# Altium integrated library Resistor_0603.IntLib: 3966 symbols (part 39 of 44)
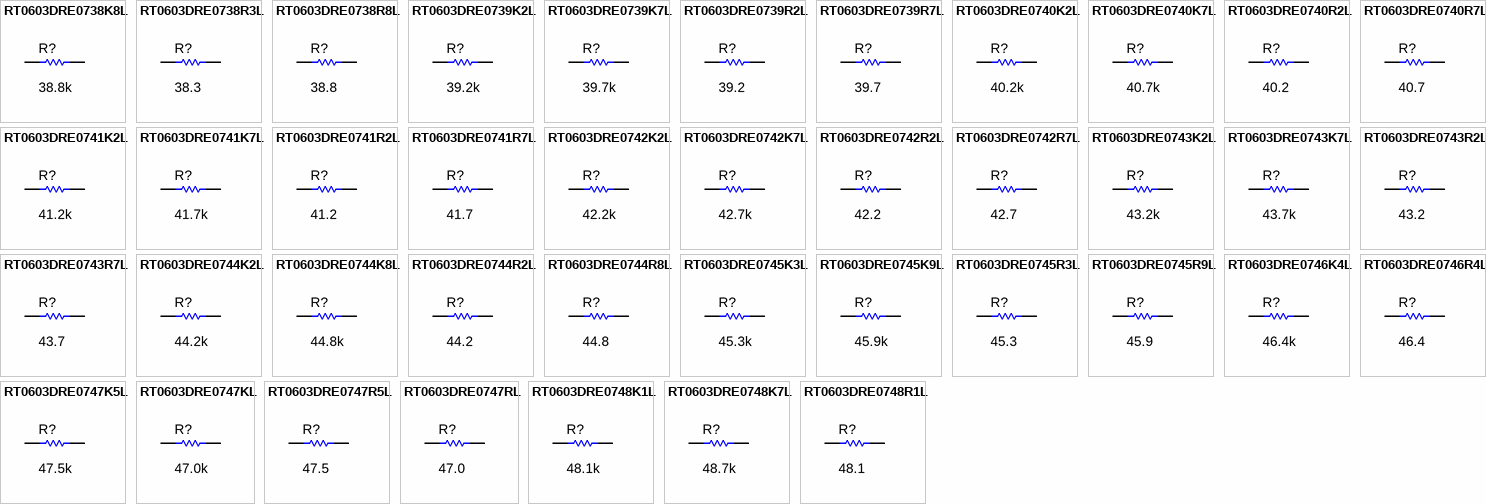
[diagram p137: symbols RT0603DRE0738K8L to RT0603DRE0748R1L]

## RT0603DRE0745R9L
designator R?  ValueDisplayed: 45.9  (hidden comment: RT0603DRE0745R9L)
RES, 45.9, 0.5%, 0.1 W, 0603; Manufacturer: Yageo America; CompType: Resistor; Value: 45.9; Value_Code: 45R9; Tolerance_%: 0.5; Power_W: 0.1; Value2: 0.1W; VDC_V: 75; TempCo: 50 ppm/C; SizeArea_mm2: 1.28; SizeX_mm: 1.6; SizeY_mm: 0.8; SizeZ_mm: 1; EIA_Code: E192; U/M: EA; AEC Category: Q200
signal-integrity model Resistor
simulation model Resistor
footprint 0603
footprint 0603M
footprint 0603L
footprint 0603_HV
footprint 0603S
pins: 1, 2

## RT0603DRE0746K4L
designator R?  ValueDisplayed: 46.4k  (hidden comment: RT0603DRE0746K4L)
RES, 46.4 k, 0.5%, 0.1 W, 0603; Manufacturer: Yageo America; CompType: Resistor; Value: 46.4k; Res_ohm: 46400; Value_Code: 46k4; Tolerance_%: 0.5; Power_W: 0.1; Value2: 0.1W; VDC_V: 75; TempCo: 50 ppm/C; SizeArea_mm2: 1.28; SizeX_mm: 1.6; SizeY_mm: 0.8; SizeZ_mm: 1; EIA_Code: E192; U/M: EA; AEC Category: Q200
signal-integrity model Resistor
simulation model Resistor
footprint 0603
footprint 0603M
footprint 0603L
footprint 0603_HV
footprint 0603S
pins: 1, 2

## RT0603DRE0746R4L
designator R?  ValueDisplayed: 46.4  (hidden comment: RT0603DRE0746R4L)
RES, 46.4, 0.5%, 0.1 W, 0603; Manufacturer: Yageo America; CompType: Resistor; Value: 46.4; Value_Code: 46R4; Tolerance_%: 0.5; Power_W: 0.1; Value2: 0.1W; VDC_V: 75; TempCo: 50 ppm/C; SizeArea_mm2: 1.28; SizeX_mm: 1.6; SizeY_mm: 0.8; SizeZ_mm: 1; EIA_Code: E192; U/M: EA; AEC Category: Q200
signal-integrity model Resistor
simulation model Resistor
footprint 0603
footprint 0603M
footprint 0603L
footprint 0603_HV
footprint 0603S
pins: 1, 2

## RT0603DRE0747K5L
designator R?  ValueDisplayed: 47.5k  (hidden comment: RT0603DRE0747K5L)
RES, 47.5 k, 0.5%, 0.1 W, 0603; Manufacturer: Yageo America; CompType: Resistor; Value: 47.5k; Res_ohm: 47500; Value_Code: 47k5; Tolerance_%: 0.5; Power_W: 0.1; Value2: 0.1W; VDC_V: 75; TempCo: 50 ppm/C; SizeArea_mm2: 1.28; SizeX_mm: 1.6; SizeY_mm: 0.8; SizeZ_mm: 1; EIA_Code: E192; U/M: EA; AEC Category: Q200
signal-integrity model Resistor
simulation model Resistor
footprint 0603
footprint 0603M
footprint 0603L
footprint 0603_HV
footprint 0603S
pins: 1, 2

## RT0603DRE0747KL
designator R?  ValueDisplayed: 47.0k  (hidden comment: RT0603DRE0747KL)
RES, 47.0 k, 0.5%, 0.1 W, 0603; Manufacturer: Yageo America; CompType: Resistor; Value: 47.0k; Res_ohm: 47000; Value_Code: 47k0; Tolerance_%: 0.5; Power_W: 0.1; Value2: 0.1W; VDC_V: 75; TempCo: 50 ppm/C; SizeArea_mm2: 1.28; SizeX_mm: 1.6; SizeY_mm: 0.8; SizeZ_mm: 1; EIA_Code: E192; U/M: EA; AEC Category: Q200
signal-integrity model Resistor
simulation model Resistor
footprint 0603
footprint 0603M
footprint 0603L
footprint 0603_HV
footprint 0603S
pins: 1, 2

## RT0603DRE0747R5L
designator R?  ValueDisplayed: 47.5  (hidden comment: RT0603DRE0747R5L)
RES, 47.5, 0.5%, 0.1 W, 0603; Manufacturer: Yageo America; CompType: Resistor; Value: 47.5; Value_Code: 47R5; Tolerance_%: 0.5; Power_W: 0.1; Value2: 0.1W; VDC_V: 75; TempCo: 50 ppm/C; SizeArea_mm2: 1.28; SizeX_mm: 1.6; SizeY_mm: 0.8; SizeZ_mm: 1; EIA_Code: E192; U/M: EA; AEC Category: Q200
signal-integrity model Resistor
simulation model Resistor
footprint 0603
footprint 0603M
footprint 0603L
footprint 0603_HV
footprint 0603S
pins: 1, 2

## RT0603DRE0747RL
designator R?  ValueDisplayed: 47.0  (hidden comment: RT0603DRE0747RL)
RES, 47.0, 0.5%, 0.1 W, 0603; Manufacturer: Yageo America; CompType: Resistor; Value: 47.0; Res_ohm: 47; Value_Code: 47R0; Tolerance_%: 0.5; Power_W: 0.1; Value2: 0.1W; VDC_V: 75; TempCo: 50 ppm/C; SizeArea_mm2: 1.28; SizeX_mm: 1.6; SizeY_mm: 0.8; SizeZ_mm: 1; EIA_Code: E192; U/M: EA; AEC Category: Q200
signal-integrity model Resistor
simulation model Resistor
footprint 0603
footprint 0603M
footprint 0603L
footprint 0603_HV
footprint 0603S
pins: 1, 2

## RT0603DRE0748K1L
designator R?  ValueDisplayed: 48.1k  (hidden comment: RT0603DRE0748K1L)
RES, 48.1 k, 0.5%, 0.1 W, 0603; Manufacturer: Yageo America; CompType: Resistor; Value: 48.1k; Res_ohm: 48100; Value_Code: 48k1; Tolerance_%: 0.5; Power_W: 0.1; Value2: 0.1W; VDC_V: 75; TempCo: 50 ppm/C; SizeArea_mm2: 1.28; SizeX_mm: 1.6; SizeY_mm: 0.8; SizeZ_mm: 1; EIA_Code: E192; U/M: EA; AEC Category: Q200
signal-integrity model Resistor
simulation model Resistor
footprint 0603
footprint 0603M
footprint 0603L
footprint 0603_HV
footprint 0603S
pins: 1, 2

## RT0603DRE0748K7L
designator R?  ValueDisplayed: 48.7k  (hidden comment: RT0603DRE0748K7L)
RES, 48.7 k, 0.5%, 0.1 W, 0603; Manufacturer: Yageo America; CompType: Resistor; Value: 48.7k; Res_ohm: 48700; Value_Code: 48k7; Tolerance_%: 0.5; Power_W: 0.1; Value2: 0.1W; VDC_V: 75; TempCo: 50 ppm/C; SizeArea_mm2: 1.28; SizeX_mm: 1.6; SizeY_mm: 0.8; SizeZ_mm: 1; EIA_Code: E192; U/M: EA; AEC Category: Q200
signal-integrity model Resistor
simulation model Resistor
footprint 0603
footprint 0603M
footprint 0603L
footprint 0603_HV
footprint 0603S
pins: 1, 2

## RT0603DRE0748R1L
designator R?  ValueDisplayed: 48.1  (hidden comment: RT0603DRE0748R1L)
RES, 48.1, 0.5%, 0.1 W, 0603; Manufacturer: Yageo America; CompType: Resistor; Value: 48.1; Value_Code: 48R1; Tolerance_%: 0.5; Power_W: 0.1; Value2: 0.1W; VDC_V: 75; TempCo: 50 ppm/C; SizeArea_mm2: 1.28; SizeX_mm: 1.6; SizeY_mm: 0.8; SizeZ_mm: 1; EIA_Code: E192; U/M: EA; AEC Category: Q200
signal-integrity model Resistor
simulation model Resistor
footprint 0603
footprint 0603M
footprint 0603L
footprint 0603_HV
footprint 0603S
pins: 1, 2

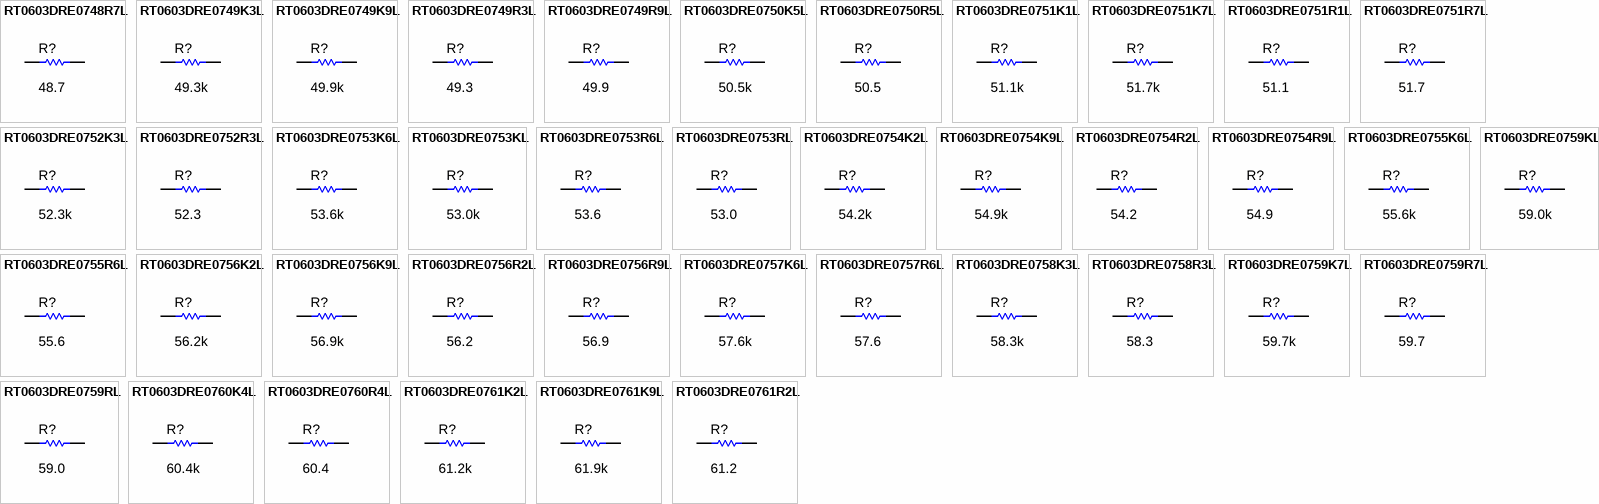
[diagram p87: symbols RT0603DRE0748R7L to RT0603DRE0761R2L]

## RT0603DRE0748R7L
designator R?  ValueDisplayed: 48.7  (hidden comment: RT0603DRE0748R7L)
RES, 48.7, 0.5%, 0.1 W, 0603; Manufacturer: Yageo America; CompType: Resistor; Value: 48.7; Value_Code: 48R7; Tolerance_%: 0.5; Power_W: 0.1; Value2: 0.1W; VDC_V: 75; TempCo: 50 ppm/C; SizeArea_mm2: 1.28; SizeX_mm: 1.6; SizeY_mm: 0.8; SizeZ_mm: 1; EIA_Code: E192; U/M: EA; AEC Category: Q200
signal-integrity model Resistor
simulation model Resistor
footprint 0603
footprint 0603M
footprint 0603L
footprint 0603_HV
footprint 0603S
pins: 1, 2

## RT0603DRE0749K3L
designator R?  ValueDisplayed: 49.3k  (hidden comment: RT0603DRE0749K3L)
RES, 49.3 k, 0.5%, 0.1 W, 0603; Manufacturer: Yageo America; CompType: Resistor; Value: 49.3k; Res_ohm: 49300; Value_Code: 49k3; Tolerance_%: 0.5; Power_W: 0.1; Value2: 0.1W; VDC_V: 75; TempCo: 50 ppm/C; SizeArea_mm2: 1.28; SizeX_mm: 1.6; SizeY_mm: 0.8; SizeZ_mm: 1; EIA_Code: E192; U/M: EA; AEC Category: Q200
signal-integrity model Resistor
simulation model Resistor
footprint 0603
footprint 0603M
footprint 0603L
footprint 0603_HV
footprint 0603S
pins: 1, 2

## RT0603DRE0749K9L
designator R?  ValueDisplayed: 49.9k  (hidden comment: RT0603DRE0749K9L)
RES, 49.9 k, 0.5%, 0.1 W, 0603; Manufacturer: Yageo America; CompType: Resistor; Value: 49.9k; Res_ohm: 49900; Value_Code: 49k9; Tolerance_%: 0.5; Power_W: 0.1; Value2: 0.1W; VDC_V: 75; TempCo: 50 ppm/C; SizeArea_mm2: 1.28; SizeX_mm: 1.6; SizeY_mm: 0.8; SizeZ_mm: 1; EIA_Code: E192; U/M: EA; AEC Category: Q200
signal-integrity model Resistor
simulation model Resistor
footprint 0603
footprint 0603M
footprint 0603L
footprint 0603_HV
footprint 0603S
pins: 1, 2

## RT0603DRE0749R3L
designator R?  ValueDisplayed: 49.3  (hidden comment: RT0603DRE0749R3L)
RES, 49.3, 0.5%, 0.1 W, 0603; Manufacturer: Yageo America; CompType: Resistor; Value: 49.3; Value_Code: 49R3; Tolerance_%: 0.5; Power_W: 0.1; Value2: 0.1W; VDC_V: 75; TempCo: 50 ppm/C; SizeArea_mm2: 1.28; SizeX_mm: 1.6; SizeY_mm: 0.8; SizeZ_mm: 1; EIA_Code: E192; U/M: EA; AEC Category: Q200
signal-integrity model Resistor
simulation model Resistor
footprint 0603
footprint 0603M
footprint 0603L
footprint 0603_HV
footprint 0603S
pins: 1, 2

## RT0603DRE0749R9L
designator R?  ValueDisplayed: 49.9  (hidden comment: RT0603DRE0749R9L)
RES, 49.9, 0.5%, 0.1 W, 0603; Manufacturer: Yageo America; CompType: Resistor; Value: 49.9; Value_Code: 49R9; Tolerance_%: 0.5; Power_W: 0.1; Value2: 0.1W; VDC_V: 75; TempCo: 50 ppm/C; SizeArea_mm2: 1.28; SizeX_mm: 1.6; SizeY_mm: 0.8; SizeZ_mm: 1; EIA_Code: E192; U/M: EA; AEC Category: Q200
signal-integrity model Resistor
simulation model Resistor
footprint 0603
footprint 0603M
footprint 0603L
footprint 0603_HV
footprint 0603S
pins: 1, 2

## RT0603DRE0750K5L
designator R?  ValueDisplayed: 50.5k  (hidden comment: RT0603DRE0750K5L)
RES, 50.5 k, 0.5%, 0.1 W, 0603; Manufacturer: Yageo America; CompType: Resistor; Value: 50.5k; Res_ohm: 50500; Value_Code: 50k5; Tolerance_%: 0.5; Power_W: 0.1; Value2: 0.1W; VDC_V: 75; TempCo: 50 ppm/C; SizeArea_mm2: 1.28; SizeX_mm: 1.6; SizeY_mm: 0.8; SizeZ_mm: 1; EIA_Code: E192; U/M: EA; AEC Category: Q200
signal-integrity model Resistor
simulation model Resistor
footprint 0603
footprint 0603M
footprint 0603L
footprint 0603_HV
footprint 0603S
pins: 1, 2

## RT0603DRE0750R5L
designator R?  ValueDisplayed: 50.5  (hidden comment: RT0603DRE0750R5L)
RES, 50.5, 0.5%, 0.1 W, 0603; Manufacturer: Yageo America; CompType: Resistor; Value: 50.5; Value_Code: 50R5; Tolerance_%: 0.5; Power_W: 0.1; Value2: 0.1W; VDC_V: 75; TempCo: 50 ppm/C; SizeArea_mm2: 1.28; SizeX_mm: 1.6; SizeY_mm: 0.8; SizeZ_mm: 1; EIA_Code: E192; U/M: EA; AEC Category: Q200
signal-integrity model Resistor
simulation model Resistor
footprint 0603
footprint 0603M
footprint 0603L
footprint 0603_HV
footprint 0603S
pins: 1, 2

## RT0603DRE0751K1L
designator R?  ValueDisplayed: 51.1k  (hidden comment: RT0603DRE0751K1L)
RES, 51.1 k, 0.5%, 0.1 W, 0603; Manufacturer: Yageo America; CompType: Resistor; Value: 51.1k; Res_ohm: 51100; Value_Code: 51k1; Tolerance_%: 0.5; Power_W: 0.1; Value2: 0.1W; VDC_V: 75; TempCo: 50 ppm/C; SizeArea_mm2: 1.28; SizeX_mm: 1.6; SizeY_mm: 0.8; SizeZ_mm: 1; EIA_Code: E192; U/M: EA; AEC Category: Q200
signal-integrity model Resistor
simulation model Resistor
footprint 0603
footprint 0603M
footprint 0603L
footprint 0603_HV
footprint 0603S
pins: 1, 2

## RT0603DRE0751K7L
designator R?  ValueDisplayed: 51.7k  (hidden comment: RT0603DRE0751K7L)
RES, 51.7 k, 0.5%, 0.1 W, 0603; Manufacturer: Yageo America; CompType: Resistor; Value: 51.7k; Res_ohm: 51700; Value_Code: 51k7; Tolerance_%: 0.5; Power_W: 0.1; Value2: 0.1W; VDC_V: 75; TempCo: 50 ppm/C; SizeArea_mm2: 1.28; SizeX_mm: 1.6; SizeY_mm: 0.8; SizeZ_mm: 1; EIA_Code: E192; U/M: EA; AEC Category: Q200
signal-integrity model Resistor
simulation model Resistor
footprint 0603
footprint 0603M
footprint 0603L
footprint 0603_HV
footprint 0603S
pins: 1, 2

## RT0603DRE0751R1L
designator R?  ValueDisplayed: 51.1  (hidden comment: RT0603DRE0751R1L)
RES, 51.1, 0.5%, 0.1 W, 0603; Manufacturer: Yageo America; CompType: Resistor; Value: 51.1; Value_Code: 51R1; Tolerance_%: 0.5; Power_W: 0.1; Value2: 0.1W; VDC_V: 75; TempCo: 50 ppm/C; SizeArea_mm2: 1.28; SizeX_mm: 1.6; SizeY_mm: 0.8; SizeZ_mm: 1; EIA_Code: E192; U/M: EA; AEC Category: Q200
signal-integrity model Resistor
simulation model Resistor
footprint 0603
footprint 0603M
footprint 0603L
footprint 0603_HV
footprint 0603S
pins: 1, 2

## RT0603DRE0751R7L
designator R?  ValueDisplayed: 51.7  (hidden comment: RT0603DRE0751R7L)
RES, 51.7, 0.5%, 0.1 W, 0603; Manufacturer: Yageo America; CompType: Resistor; Value: 51.7; Value_Code: 51R7; Tolerance_%: 0.5; Power_W: 0.1; Value2: 0.1W; VDC_V: 75; TempCo: 50 ppm/C; SizeArea_mm2: 1.28; SizeX_mm: 1.6; SizeY_mm: 0.8; SizeZ_mm: 1; EIA_Code: E192; U/M: EA; AEC Category: Q200
signal-integrity model Resistor
simulation model Resistor
footprint 0603
footprint 0603M
footprint 0603L
footprint 0603_HV
footprint 0603S
pins: 1, 2

## RT0603DRE0752K3L
designator R?  ValueDisplayed: 52.3k  (hidden comment: RT0603DRE0752K3L)
RES, 52.3 k, 0.5%, 0.1 W, 0603; Manufacturer: Yageo America; CompType: Resistor; Value: 52.3k; Res_ohm: 52300; Value_Code: 52k3; Tolerance_%: 0.5; Power_W: 0.1; Value2: 0.1W; VDC_V: 75; TempCo: 50 ppm/C; SizeArea_mm2: 1.28; SizeX_mm: 1.6; SizeY_mm: 0.8; SizeZ_mm: 1; EIA_Code: E192; U/M: EA; AEC Category: Q200
signal-integrity model Resistor
simulation model Resistor
footprint 0603
footprint 0603M
footprint 0603L
footprint 0603_HV
footprint 0603S
pins: 1, 2

## RT0603DRE0752R3L
designator R?  ValueDisplayed: 52.3  (hidden comment: RT0603DRE0752R3L)
RES, 52.3, 0.5%, 0.1 W, 0603; Manufacturer: Yageo America; CompType: Resistor; Value: 52.3; Value_Code: 52R3; Tolerance_%: 0.5; Power_W: 0.1; Value2: 0.1W; VDC_V: 75; TempCo: 50 ppm/C; SizeArea_mm2: 1.28; SizeX_mm: 1.6; SizeY_mm: 0.8; SizeZ_mm: 1; EIA_Code: E192; U/M: EA; AEC Category: Q200
signal-integrity model Resistor
simulation model Resistor
footprint 0603
footprint 0603M
footprint 0603L
footprint 0603_HV
footprint 0603S
pins: 1, 2

## RT0603DRE0753K6L
designator R?  ValueDisplayed: 53.6k  (hidden comment: RT0603DRE0753K6L)
RES, 53.6 k, 0.5%, 0.1 W, 0603; Manufacturer: Yageo America; CompType: Resistor; Value: 53.6k; Res_ohm: 53600; Value_Code: 53k6; Tolerance_%: 0.5; Power_W: 0.1; Value2: 0.1W; VDC_V: 75; TempCo: 50 ppm/C; SizeArea_mm2: 1.28; SizeX_mm: 1.6; SizeY_mm: 0.8; SizeZ_mm: 1; EIA_Code: E192; U/M: EA; AEC Category: Q200
signal-integrity model Resistor
simulation model Resistor
footprint 0603
footprint 0603M
footprint 0603L
footprint 0603_HV
footprint 0603S
pins: 1, 2

## RT0603DRE0753KL
designator R?  ValueDisplayed: 53.0k  (hidden comment: RT0603DRE0753KL)
RES, 53.0 k, 0.5%, 0.1 W, 0603; Manufacturer: Yageo America; CompType: Resistor; Value: 53.0k; Res_ohm: 53000; Value_Code: 53k0; Tolerance_%: 0.5; Power_W: 0.1; Value2: 0.1W; VDC_V: 75; TempCo: 50 ppm/C; SizeArea_mm2: 1.28; SizeX_mm: 1.6; SizeY_mm: 0.8; SizeZ_mm: 1; EIA_Code: E192; U/M: EA; AEC Category: Q200
signal-integrity model Resistor
simulation model Resistor
footprint 0603
footprint 0603M
footprint 0603L
footprint 0603_HV
footprint 0603S
pins: 1, 2

## RT0603DRE0753R6L
designator R?  ValueDisplayed: 53.6  (hidden comment: RT0603DRE0753R6L)
RES, 53.6, 0.5%, 0.1 W, 0603; Manufacturer: Yageo America; CompType: Resistor; Value: 53.6; Value_Code: 53R6; Tolerance_%: 0.5; Power_W: 0.1; Value2: 0.1W; VDC_V: 75; TempCo: 50 ppm/C; SizeArea_mm2: 1.28; SizeX_mm: 1.6; SizeY_mm: 0.8; SizeZ_mm: 1; EIA_Code: E192; U/M: EA; AEC Category: Q200
signal-integrity model Resistor
simulation model Resistor
footprint 0603
footprint 0603M
footprint 0603L
footprint 0603_HV
footprint 0603S
pins: 1, 2

## RT0603DRE0753RL
designator R?  ValueDisplayed: 53.0  (hidden comment: RT0603DRE0753RL)
RES, 53.0, 0.5%, 0.1 W, 0603; Manufacturer: Yageo America; CompType: Resistor; Value: 53.0; Res_ohm: 53; Value_Code: 53R0; Tolerance_%: 0.5; Power_W: 0.1; Value2: 0.1W; VDC_V: 75; TempCo: 50 ppm/C; SizeArea_mm2: 1.28; SizeX_mm: 1.6; SizeY_mm: 0.8; SizeZ_mm: 1; EIA_Code: E192; U/M: EA; AEC Category: Q200
signal-integrity model Resistor
simulation model Resistor
footprint 0603
footprint 0603M
footprint 0603L
footprint 0603_HV
footprint 0603S
pins: 1, 2

## RT0603DRE0754K2L
designator R?  ValueDisplayed: 54.2k  (hidden comment: RT0603DRE0754K2L)
RES, 54.2 k, 0.5%, 0.1 W, 0603; Manufacturer: Yageo America; CompType: Resistor; Value: 54.2k; Res_ohm: 54200; Value_Code: 54k2; Tolerance_%: 0.5; Power_W: 0.1; Value2: 0.1W; VDC_V: 75; TempCo: 50 ppm/C; SizeArea_mm2: 1.28; SizeX_mm: 1.6; SizeY_mm: 0.8; SizeZ_mm: 1; EIA_Code: E192; U/M: EA; AEC Category: Q200
signal-integrity model Resistor
simulation model Resistor
footprint 0603
footprint 0603M
footprint 0603L
footprint 0603_HV
footprint 0603S
pins: 1, 2

## RT0603DRE0754K9L
designator R?  ValueDisplayed: 54.9k  (hidden comment: RT0603DRE0754K9L)
RES, 54.9 k, 0.5%, 0.1 W, 0603; Manufacturer: Yageo America; CompType: Resistor; Value: 54.9k; Res_ohm: 54900; Value_Code: 54k9; Tolerance_%: 0.5; Power_W: 0.1; Value2: 0.1W; VDC_V: 75; TempCo: 50 ppm/C; SizeArea_mm2: 1.28; SizeX_mm: 1.6; SizeY_mm: 0.8; SizeZ_mm: 1; EIA_Code: E192; U/M: EA; AEC Category: Q200
signal-integrity model Resistor
simulation model Resistor
footprint 0603
footprint 0603M
footprint 0603L
footprint 0603_HV
footprint 0603S
pins: 1, 2

## RT0603DRE0754R2L
designator R?  ValueDisplayed: 54.2  (hidden comment: RT0603DRE0754R2L)
RES, 54.2, 0.5%, 0.1 W, 0603; Manufacturer: Yageo America; CompType: Resistor; Value: 54.2; Value_Code: 54R2; Tolerance_%: 0.5; Power_W: 0.1; Value2: 0.1W; VDC_V: 75; TempCo: 50 ppm/C; SizeArea_mm2: 1.28; SizeX_mm: 1.6; SizeY_mm: 0.8; SizeZ_mm: 1; EIA_Code: E192; U/M: EA; AEC Category: Q200
signal-integrity model Resistor
simulation model Resistor
footprint 0603
footprint 0603M
footprint 0603L
footprint 0603_HV
footprint 0603S
pins: 1, 2

## RT0603DRE0754R9L
designator R?  ValueDisplayed: 54.9  (hidden comment: RT0603DRE0754R9L)
RES, 54.9, 0.5%, 0.1 W, 0603; Manufacturer: Yageo America; CompType: Resistor; Value: 54.9; Value_Code: 54R9; Tolerance_%: 0.5; Power_W: 0.1; Value2: 0.1W; VDC_V: 75; TempCo: 50 ppm/C; SizeArea_mm2: 1.28; SizeX_mm: 1.6; SizeY_mm: 0.8; SizeZ_mm: 1; EIA_Code: E192; U/M: EA; AEC Category: Q200
signal-integrity model Resistor
simulation model Resistor
footprint 0603
footprint 0603M
footprint 0603L
footprint 0603_HV
footprint 0603S
pins: 1, 2

## RT0603DRE0755K6L
designator R?  ValueDisplayed: 55.6k  (hidden comment: RT0603DRE0755K6L)
RES, 55.6 k, 0.5%, 0.1 W, 0603; Manufacturer: Yageo America; CompType: Resistor; Value: 55.6k; Res_ohm: 55600; Value_Code: 55k6; Tolerance_%: 0.5; Power_W: 0.1; Value2: 0.1W; VDC_V: 75; TempCo: 50 ppm/C; SizeArea_mm2: 1.28; SizeX_mm: 1.6; SizeY_mm: 0.8; SizeZ_mm: 1; EIA_Code: E192; U/M: EA; AEC Category: Q200
signal-integrity model Resistor
simulation model Resistor
footprint 0603
footprint 0603M
footprint 0603L
footprint 0603_HV
footprint 0603S
pins: 1, 2

## RT0603DRE0755R6L
designator R?  ValueDisplayed: 55.6  (hidden comment: RT0603DRE0755R6L)
RES, 55.6, 0.5%, 0.1 W, 0603; Manufacturer: Yageo America; CompType: Resistor; Value: 55.6; Value_Code: 55R6; Tolerance_%: 0.5; Power_W: 0.1; Value2: 0.1W; VDC_V: 75; TempCo: 50 ppm/C; SizeArea_mm2: 1.28; SizeX_mm: 1.6; SizeY_mm: 0.8; SizeZ_mm: 1; EIA_Code: E192; U/M: EA; AEC Category: Q200
signal-integrity model Resistor
simulation model Resistor
footprint 0603
footprint 0603M
footprint 0603L
footprint 0603_HV
footprint 0603S
pins: 1, 2

## RT0603DRE0756K2L
designator R?  ValueDisplayed: 56.2k  (hidden comment: RT0603DRE0756K2L)
RES, 56.2 k, 0.5%, 0.1 W, 0603; Manufacturer: Yageo America; CompType: Resistor; Value: 56.2k; Res_ohm: 56200; Value_Code: 56k2; Tolerance_%: 0.5; Power_W: 0.1; Value2: 0.1W; VDC_V: 75; TempCo: 50 ppm/C; SizeArea_mm2: 1.28; SizeX_mm: 1.6; SizeY_mm: 0.8; SizeZ_mm: 1; EIA_Code: E192; U/M: EA; AEC Category: Q200
signal-integrity model Resistor
simulation model Resistor
footprint 0603
footprint 0603M
footprint 0603L
footprint 0603_HV
footprint 0603S
pins: 1, 2

## RT0603DRE0756K9L
designator R?  ValueDisplayed: 56.9k  (hidden comment: RT0603DRE0756K9L)
RES, 56.9 k, 0.5%, 0.1 W, 0603; Manufacturer: Yageo America; CompType: Resistor; Value: 56.9k; Res_ohm: 56900; Value_Code: 56k9; Tolerance_%: 0.5; Power_W: 0.1; Value2: 0.1W; VDC_V: 75; TempCo: 50 ppm/C; SizeArea_mm2: 1.28; SizeX_mm: 1.6; SizeY_mm: 0.8; SizeZ_mm: 1; EIA_Code: E192; U/M: EA; AEC Category: Q200
signal-integrity model Resistor
simulation model Resistor
footprint 0603
footprint 0603M
footprint 0603L
footprint 0603_HV
footprint 0603S
pins: 1, 2

## RT0603DRE0756R2L
designator R?  ValueDisplayed: 56.2  (hidden comment: RT0603DRE0756R2L)
RES, 56.2, 0.5%, 0.1 W, 0603; Manufacturer: Yageo America; CompType: Resistor; Value: 56.2; Value_Code: 56R2; Tolerance_%: 0.5; Power_W: 0.1; Value2: 0.1W; VDC_V: 75; TempCo: 50 ppm/C; SizeArea_mm2: 1.28; SizeX_mm: 1.6; SizeY_mm: 0.8; SizeZ_mm: 1; EIA_Code: E192; U/M: EA; AEC Category: Q200
signal-integrity model Resistor
simulation model Resistor
footprint 0603
footprint 0603M
footprint 0603L
footprint 0603_HV
footprint 0603S
pins: 1, 2

## RT0603DRE0756R9L
designator R?  ValueDisplayed: 56.9  (hidden comment: RT0603DRE0756R9L)
RES, 56.9, 0.5%, 0.1 W, 0603; Manufacturer: Yageo America; CompType: Resistor; Value: 56.9; Value_Code: 56R9; Tolerance_%: 0.5; Power_W: 0.1; Value2: 0.1W; VDC_V: 75; TempCo: 50 ppm/C; SizeArea_mm2: 1.28; SizeX_mm: 1.6; SizeY_mm: 0.8; SizeZ_mm: 1; EIA_Code: E192; U/M: EA; AEC Category: Q200
signal-integrity model Resistor
simulation model Resistor
footprint 0603
footprint 0603M
footprint 0603L
footprint 0603_HV
footprint 0603S
pins: 1, 2

## RT0603DRE0757K6L
designator R?  ValueDisplayed: 57.6k  (hidden comment: RT0603DRE0757K6L)
RES, 57.6 k, 0.5%, 0.1 W, 0603; Manufacturer: Yageo America; CompType: Resistor; Value: 57.6k; Res_ohm: 57600; Value_Code: 57k6; Tolerance_%: 0.5; Power_W: 0.1; Value2: 0.1W; VDC_V: 75; TempCo: 50 ppm/C; SizeArea_mm2: 1.28; SizeX_mm: 1.6; SizeY_mm: 0.8; SizeZ_mm: 1; EIA_Code: E192; U/M: EA; AEC Category: Q200
signal-integrity model Resistor
simulation model Resistor
footprint 0603
footprint 0603M
footprint 0603L
footprint 0603_HV
footprint 0603S
pins: 1, 2

## RT0603DRE0757R6L
designator R?  ValueDisplayed: 57.6  (hidden comment: RT0603DRE0757R6L)
RES, 57.6, 0.5%, 0.1 W, 0603; Manufacturer: Yageo America; CompType: Resistor; Value: 57.6; Value_Code: 57R6; Tolerance_%: 0.5; Power_W: 0.1; Value2: 0.1W; VDC_V: 75; TempCo: 50 ppm/C; SizeArea_mm2: 1.28; SizeX_mm: 1.6; SizeY_mm: 0.8; SizeZ_mm: 1; EIA_Code: E192; U/M: EA; AEC Category: Q200
signal-integrity model Resistor
simulation model Resistor
footprint 0603
footprint 0603M
footprint 0603L
footprint 0603_HV
footprint 0603S
pins: 1, 2

## RT0603DRE0758K3L
designator R?  ValueDisplayed: 58.3k  (hidden comment: RT0603DRE0758K3L)
RES, 58.3 k, 0.5%, 0.1 W, 0603; Manufacturer: Yageo America; CompType: Resistor; Value: 58.3k; Res_ohm: 58300; Value_Code: 58k3; Tolerance_%: 0.5; Power_W: 0.1; Value2: 0.1W; VDC_V: 75; TempCo: 50 ppm/C; SizeArea_mm2: 1.28; SizeX_mm: 1.6; SizeY_mm: 0.8; SizeZ_mm: 1; EIA_Code: E192; U/M: EA; AEC Category: Q200
signal-integrity model Resistor
simulation model Resistor
footprint 0603
footprint 0603M
footprint 0603L
footprint 0603_HV
footprint 0603S
pins: 1, 2

## RT0603DRE0758R3L
designator R?  ValueDisplayed: 58.3  (hidden comment: RT0603DRE0758R3L)
RES, 58.3, 0.5%, 0.1 W, 0603; Manufacturer: Yageo America; CompType: Resistor; Value: 58.3; Value_Code: 58R3; Tolerance_%: 0.5; Power_W: 0.1; Value2: 0.1W; VDC_V: 75; TempCo: 50 ppm/C; SizeArea_mm2: 1.28; SizeX_mm: 1.6; SizeY_mm: 0.8; SizeZ_mm: 1; EIA_Code: E192; U/M: EA; AEC Category: Q200
signal-integrity model Resistor
simulation model Resistor
footprint 0603
footprint 0603M
footprint 0603L
footprint 0603_HV
footprint 0603S
pins: 1, 2

## RT0603DRE0759K7L
designator R?  ValueDisplayed: 59.7k  (hidden comment: RT0603DRE0759K7L)
RES, 59.7 k, 0.5%, 0.1 W, 0603; Manufacturer: Yageo America; CompType: Resistor; Value: 59.7k; Res_ohm: 59700; Value_Code: 59k7; Tolerance_%: 0.5; Power_W: 0.1; Value2: 0.1W; VDC_V: 75; TempCo: 50 ppm/C; SizeArea_mm2: 1.28; SizeX_mm: 1.6; SizeY_mm: 0.8; SizeZ_mm: 1; EIA_Code: E192; U/M: EA; AEC Category: Q200
signal-integrity model Resistor
simulation model Resistor
footprint 0603
footprint 0603M
footprint 0603L
footprint 0603_HV
footprint 0603S
pins: 1, 2

## RT0603DRE0759KL
designator R?  ValueDisplayed: 59.0k  (hidden comment: RT0603DRE0759KL)
RES, 59.0 k, 0.5%, 0.1 W, 0603; Manufacturer: Yageo America; CompType: Resistor; Value: 59.0k; Res_ohm: 59000; Value_Code: 59k0; Tolerance_%: 0.5; Power_W: 0.1; Value2: 0.1W; VDC_V: 75; TempCo: 50 ppm/C; SizeArea_mm2: 1.28; SizeX_mm: 1.6; SizeY_mm: 0.8; SizeZ_mm: 1; EIA_Code: E192; U/M: EA; AEC Category: Q200
signal-integrity model Resistor
simulation model Resistor
footprint 0603
footprint 0603M
footprint 0603L
footprint 0603_HV
footprint 0603S
pins: 1, 2

## RT0603DRE0759R7L
designator R?  ValueDisplayed: 59.7  (hidden comment: RT0603DRE0759R7L)
RES, 59.7, 0.5%, 0.1 W, 0603; Manufacturer: Yageo America; CompType: Resistor; Value: 59.7; Value_Code: 59R7; Tolerance_%: 0.5; Power_W: 0.1; Value2: 0.1W; VDC_V: 75; TempCo: 50 ppm/C; SizeArea_mm2: 1.28; SizeX_mm: 1.6; SizeY_mm: 0.8; SizeZ_mm: 1; EIA_Code: E192; U/M: EA; AEC Category: Q200
signal-integrity model Resistor
simulation model Resistor
footprint 0603
footprint 0603M
footprint 0603L
footprint 0603_HV
footprint 0603S
pins: 1, 2

## RT0603DRE0759RL
designator R?  ValueDisplayed: 59.0  (hidden comment: RT0603DRE0759RL)
RES, 59.0, 0.5%, 0.1 W, 0603; Manufacturer: Yageo America; CompType: Resistor; Value: 59.0; Res_ohm: 59; Value_Code: 59R0; Tolerance_%: 0.5; Power_W: 0.1; Value2: 0.1W; VDC_V: 75; TempCo: 50 ppm/C; SizeArea_mm2: 1.28; SizeX_mm: 1.6; SizeY_mm: 0.8; SizeZ_mm: 1; EIA_Code: E192; U/M: EA; AEC Category: Q200
signal-integrity model Resistor
simulation model Resistor
footprint 0603
footprint 0603M
footprint 0603L
footprint 0603_HV
footprint 0603S
pins: 1, 2

## RT0603DRE0760K4L
designator R?  ValueDisplayed: 60.4k  (hidden comment: RT0603DRE0760K4L)
RES, 60.4 k, 0.5%, 0.1 W, 0603; Manufacturer: Yageo America; CompType: Resistor; Value: 60.4k; Res_ohm: 60400; Value_Code: 60k4; Tolerance_%: 0.5; Power_W: 0.1; Value2: 0.1W; VDC_V: 75; TempCo: 50 ppm/C; SizeArea_mm2: 1.28; SizeX_mm: 1.6; SizeY_mm: 0.8; SizeZ_mm: 1; EIA_Code: E192; U/M: EA; AEC Category: Q200; Green_Lifecycle: Active; Green_REACh: Passed
signal-integrity model Resistor
simulation model Resistor
footprint 0603
footprint 0603M
footprint 0603L
footprint 0603_HV
footprint 0603S
pins: 1, 2

## RT0603DRE0760R4L
designator R?  ValueDisplayed: 60.4  (hidden comment: RT0603DRE0760R4L)
RES, 60.4, 0.5%, 0.1 W, 0603; Manufacturer: Yageo America; CompType: Resistor; Value: 60.4; Value_Code: 60R4; Tolerance_%: 0.5; Power_W: 0.1; Value2: 0.1W; VDC_V: 75; TempCo: 50 ppm/C; SizeArea_mm2: 1.28; SizeX_mm: 1.6; SizeY_mm: 0.8; SizeZ_mm: 1; EIA_Code: E192; U/M: EA; AEC Category: Q200
signal-integrity model Resistor
simulation model Resistor
footprint 0603
footprint 0603M
footprint 0603L
footprint 0603_HV
footprint 0603S
pins: 1, 2

## RT0603DRE0761K2L
designator R?  ValueDisplayed: 61.2k  (hidden comment: RT0603DRE0761K2L)
RES, 61.2 k, 0.5%, 0.1 W, 0603; Manufacturer: Yageo America; CompType: Resistor; Value: 61.2k; Res_ohm: 61200; Value_Code: 61k2; Tolerance_%: 0.5; Power_W: 0.1; Value2: 0.1W; VDC_V: 75; TempCo: 50 ppm/C; SizeArea_mm2: 1.28; SizeX_mm: 1.6; SizeY_mm: 0.8; SizeZ_mm: 1; EIA_Code: E192; U/M: EA; AEC Category: Q200
signal-integrity model Resistor
simulation model Resistor
footprint 0603
footprint 0603M
footprint 0603L
footprint 0603_HV
footprint 0603S
pins: 1, 2

## RT0603DRE0761K9L
designator R?  ValueDisplayed: 61.9k  (hidden comment: RT0603DRE0761K9L)
RES, 61.9 k, 0.5%, 0.1 W, 0603; Manufacturer: Yageo America; CompType: Resistor; Value: 61.9k; Res_ohm: 61900; Value_Code: 61k9; Tolerance_%: 0.5; Power_W: 0.1; Value2: 0.1W; VDC_V: 75; TempCo: 50 ppm/C; SizeArea_mm2: 1.28; SizeX_mm: 1.6; SizeY_mm: 0.8; SizeZ_mm: 1; EIA_Code: E192; U/M: EA; AEC Category: Q200
signal-integrity model Resistor
simulation model Resistor
footprint 0603
footprint 0603M
footprint 0603L
footprint 0603_HV
footprint 0603S
pins: 1, 2

## RT0603DRE0761R2L
designator R?  ValueDisplayed: 61.2  (hidden comment: RT0603DRE0761R2L)
RES, 61.2, 0.5%, 0.1 W, 0603; Manufacturer: Yageo America; CompType: Resistor; Value: 61.2; Value_Code: 61R2; Tolerance_%: 0.5; Power_W: 0.1; Value2: 0.1W; VDC_V: 75; TempCo: 50 ppm/C; SizeArea_mm2: 1.28; SizeX_mm: 1.6; SizeY_mm: 0.8; SizeZ_mm: 1; EIA_Code: E192; U/M: EA; AEC Category: Q200
signal-integrity model Resistor
simulation model Resistor
footprint 0603
footprint 0603M
footprint 0603L
footprint 0603_HV
footprint 0603S
pins: 1, 2

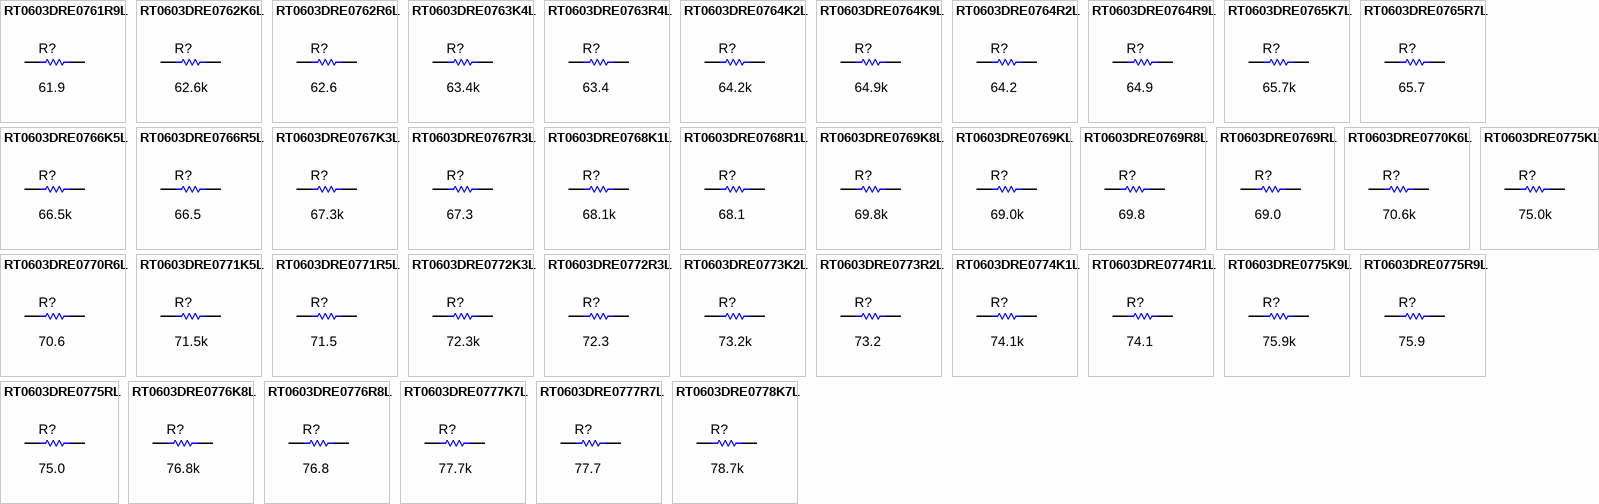
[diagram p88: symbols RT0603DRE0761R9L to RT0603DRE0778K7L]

## RT0603DRE0761R9L
designator R?  ValueDisplayed: 61.9  (hidden comment: RT0603DRE0761R9L)
RES, 61.9, 0.5%, 0.1 W, 0603; Manufacturer: Yageo America; CompType: Resistor; Value: 61.9; Value_Code: 61R9; Tolerance_%: 0.5; Power_W: 0.1; Value2: 0.1W; VDC_V: 75; TempCo: 50 ppm/C; SizeArea_mm2: 1.28; SizeX_mm: 1.6; SizeY_mm: 0.8; SizeZ_mm: 1; EIA_Code: E192; U/M: EA; AEC Category: Q200
signal-integrity model Resistor
simulation model Resistor
footprint 0603
footprint 0603M
footprint 0603L
footprint 0603_HV
footprint 0603S
pins: 1, 2

## RT0603DRE0762K6L
designator R?  ValueDisplayed: 62.6k  (hidden comment: RT0603DRE0762K6L)
RES, 62.6 k, 0.5%, 0.1 W, 0603; Manufacturer: Yageo America; CompType: Resistor; Value: 62.6k; Res_ohm: 62600; Value_Code: 62k6; Tolerance_%: 0.5; Power_W: 0.1; Value2: 0.1W; VDC_V: 75; TempCo: 50 ppm/C; SizeArea_mm2: 1.28; SizeX_mm: 1.6; SizeY_mm: 0.8; SizeZ_mm: 1; EIA_Code: E192; U/M: EA; AEC Category: Q200
signal-integrity model Resistor
simulation model Resistor
footprint 0603
footprint 0603M
footprint 0603L
footprint 0603_HV
footprint 0603S
pins: 1, 2

## RT0603DRE0762R6L
designator R?  ValueDisplayed: 62.6  (hidden comment: RT0603DRE0762R6L)
RES, 62.6, 0.5%, 0.1 W, 0603; Manufacturer: Yageo America; CompType: Resistor; Value: 62.6; Value_Code: 62R6; Tolerance_%: 0.5; Power_W: 0.1; Value2: 0.1W; VDC_V: 75; TempCo: 50 ppm/C; SizeArea_mm2: 1.28; SizeX_mm: 1.6; SizeY_mm: 0.8; SizeZ_mm: 1; EIA_Code: E192; U/M: EA; AEC Category: Q200
signal-integrity model Resistor
simulation model Resistor
footprint 0603
footprint 0603M
footprint 0603L
footprint 0603_HV
footprint 0603S
pins: 1, 2

## RT0603DRE0763K4L
designator R?  ValueDisplayed: 63.4k  (hidden comment: RT0603DRE0763K4L)
RES, 63.4 k, 0.5%, 0.1 W, 0603; Manufacturer: Yageo America; CompType: Resistor; Value: 63.4k; Res_ohm: 63400; Value_Code: 63k4; Tolerance_%: 0.5; Power_W: 0.1; Value2: 0.1W; VDC_V: 75; TempCo: 50 ppm/C; SizeArea_mm2: 1.28; SizeX_mm: 1.6; SizeY_mm: 0.8; SizeZ_mm: 1; EIA_Code: E192; U/M: EA; AEC Category: Q200
signal-integrity model Resistor
simulation model Resistor
footprint 0603
footprint 0603M
footprint 0603L
footprint 0603_HV
footprint 0603S
pins: 1, 2

## RT0603DRE0763R4L
designator R?  ValueDisplayed: 63.4  (hidden comment: RT0603DRE0763R4L)
RES, 63.4, 0.5%, 0.1 W, 0603; Manufacturer: Yageo America; CompType: Resistor; Value: 63.4; Value_Code: 63R4; Tolerance_%: 0.5; Power_W: 0.1; Value2: 0.1W; VDC_V: 75; TempCo: 50 ppm/C; SizeArea_mm2: 1.28; SizeX_mm: 1.6; SizeY_mm: 0.8; SizeZ_mm: 1; EIA_Code: E192; U/M: EA; AEC Category: Q200
signal-integrity model Resistor
simulation model Resistor
footprint 0603
footprint 0603M
footprint 0603L
footprint 0603_HV
footprint 0603S
pins: 1, 2

## RT0603DRE0764K2L
designator R?  ValueDisplayed: 64.2k  (hidden comment: RT0603DRE0764K2L)
RES, 64.2 k, 0.5%, 0.1 W, 0603; Manufacturer: Yageo America; CompType: Resistor; Value: 64.2k; Res_ohm: 64200; Value_Code: 64k2; Tolerance_%: 0.5; Power_W: 0.1; Value2: 0.1W; VDC_V: 75; TempCo: 50 ppm/C; SizeArea_mm2: 1.28; SizeX_mm: 1.6; SizeY_mm: 0.8; SizeZ_mm: 1; EIA_Code: E192; U/M: EA; AEC Category: Q200
signal-integrity model Resistor
simulation model Resistor
footprint 0603
footprint 0603M
footprint 0603L
footprint 0603_HV
footprint 0603S
pins: 1, 2

## RT0603DRE0764K9L
designator R?  ValueDisplayed: 64.9k  (hidden comment: RT0603DRE0764K9L)
RES, 64.9 k, 0.5%, 0.1 W, 0603; Manufacturer: Yageo America; CompType: Resistor; Value: 64.9k; Res_ohm: 64900; Value_Code: 64k9; Tolerance_%: 0.5; Power_W: 0.1; Value2: 0.1W; VDC_V: 75; TempCo: 50 ppm/C; SizeArea_mm2: 1.28; SizeX_mm: 1.6; SizeY_mm: 0.8; SizeZ_mm: 1; EIA_Code: E192; U/M: EA; AEC Category: Q200
signal-integrity model Resistor
simulation model Resistor
footprint 0603
footprint 0603M
footprint 0603L
footprint 0603_HV
footprint 0603S
pins: 1, 2

## RT0603DRE0764R2L
designator R?  ValueDisplayed: 64.2  (hidden comment: RT0603DRE0764R2L)
RES, 64.2, 0.5%, 0.1 W, 0603; Manufacturer: Yageo America; CompType: Resistor; Value: 64.2; Value_Code: 64R2; Tolerance_%: 0.5; Power_W: 0.1; Value2: 0.1W; VDC_V: 75; TempCo: 50 ppm/C; SizeArea_mm2: 1.28; SizeX_mm: 1.6; SizeY_mm: 0.8; SizeZ_mm: 1; EIA_Code: E192; U/M: EA; AEC Category: Q200
signal-integrity model Resistor
simulation model Resistor
footprint 0603
footprint 0603M
footprint 0603L
footprint 0603_HV
footprint 0603S
pins: 1, 2

## RT0603DRE0764R9L
designator R?  ValueDisplayed: 64.9  (hidden comment: RT0603DRE0764R9L)
RES, 64.9, 0.5%, 0.1 W, 0603; Manufacturer: Yageo America; CompType: Resistor; Value: 64.9; Value_Code: 64R9; Tolerance_%: 0.5; Power_W: 0.1; Value2: 0.1W; VDC_V: 75; TempCo: 50 ppm/C; SizeArea_mm2: 1.28; SizeX_mm: 1.6; SizeY_mm: 0.8; SizeZ_mm: 1; EIA_Code: E192; U/M: EA; AEC Category: Q200
signal-integrity model Resistor
simulation model Resistor
footprint 0603
footprint 0603M
footprint 0603L
footprint 0603_HV
footprint 0603S
pins: 1, 2

## RT0603DRE0765K7L
designator R?  ValueDisplayed: 65.7k  (hidden comment: RT0603DRE0765K7L)
RES, 65.7 k, 0.5%, 0.1 W, 0603; Manufacturer: Yageo America; CompType: Resistor; Value: 65.7k; Res_ohm: 65700; Value_Code: 65k7; Tolerance_%: 0.5; Power_W: 0.1; Value2: 0.1W; VDC_V: 75; TempCo: 50 ppm/C; SizeArea_mm2: 1.28; SizeX_mm: 1.6; SizeY_mm: 0.8; SizeZ_mm: 1; EIA_Code: E192; U/M: EA; AEC Category: Q200
signal-integrity model Resistor
simulation model Resistor
footprint 0603
footprint 0603M
footprint 0603L
footprint 0603_HV
footprint 0603S
pins: 1, 2

## RT0603DRE0765R7L
designator R?  ValueDisplayed: 65.7  (hidden comment: RT0603DRE0765R7L)
RES, 65.7, 0.5%, 0.1 W, 0603; Manufacturer: Yageo America; CompType: Resistor; Value: 65.7; Value_Code: 65R7; Tolerance_%: 0.5; Power_W: 0.1; Value2: 0.1W; VDC_V: 75; TempCo: 50 ppm/C; SizeArea_mm2: 1.28; SizeX_mm: 1.6; SizeY_mm: 0.8; SizeZ_mm: 1; EIA_Code: E192; U/M: EA; AEC Category: Q200
signal-integrity model Resistor
simulation model Resistor
footprint 0603
footprint 0603M
footprint 0603L
footprint 0603_HV
footprint 0603S
pins: 1, 2

## RT0603DRE0766K5L
designator R?  ValueDisplayed: 66.5k  (hidden comment: RT0603DRE0766K5L)
RES, 66.5 k, 0.5%, 0.1 W, 0603; Manufacturer: Yageo America; CompType: Resistor; Value: 66.5k; Res_ohm: 66500; Value_Code: 66k5; Tolerance_%: 0.5; Power_W: 0.1; Value2: 0.1W; VDC_V: 75; TempCo: 50 ppm/C; SizeArea_mm2: 1.28; SizeX_mm: 1.6; SizeY_mm: 0.8; SizeZ_mm: 1; EIA_Code: E192; U/M: EA; AEC Category: Q200
signal-integrity model Resistor
simulation model Resistor
footprint 0603
footprint 0603M
footprint 0603L
footprint 0603_HV
footprint 0603S
pins: 1, 2

## RT0603DRE0766R5L
designator R?  ValueDisplayed: 66.5  (hidden comment: RT0603DRE0766R5L)
RES, 66.5, 0.5%, 0.1 W, 0603; Manufacturer: Yageo America; CompType: Resistor; Value: 66.5; Value_Code: 66R5; Tolerance_%: 0.5; Power_W: 0.1; Value2: 0.1W; VDC_V: 75; TempCo: 50 ppm/C; SizeArea_mm2: 1.28; SizeX_mm: 1.6; SizeY_mm: 0.8; SizeZ_mm: 1; EIA_Code: E192; U/M: EA; AEC Category: Q200
signal-integrity model Resistor
simulation model Resistor
footprint 0603
footprint 0603M
footprint 0603L
footprint 0603_HV
footprint 0603S
pins: 1, 2

## RT0603DRE0767K3L
designator R?  ValueDisplayed: 67.3k  (hidden comment: RT0603DRE0767K3L)
RES, 67.3 k, 0.5%, 0.1 W, 0603; Manufacturer: Yageo America; CompType: Resistor; Value: 67.3k; Res_ohm: 67300; Value_Code: 67k3; Tolerance_%: 0.5; Power_W: 0.1; Value2: 0.1W; VDC_V: 75; TempCo: 50 ppm/C; SizeArea_mm2: 1.28; SizeX_mm: 1.6; SizeY_mm: 0.8; SizeZ_mm: 1; EIA_Code: E192; U/M: EA; AEC Category: Q200
signal-integrity model Resistor
simulation model Resistor
footprint 0603
footprint 0603M
footprint 0603L
footprint 0603_HV
footprint 0603S
pins: 1, 2

## RT0603DRE0767R3L
designator R?  ValueDisplayed: 67.3  (hidden comment: RT0603DRE0767R3L)
RES, 67.3, 0.5%, 0.1 W, 0603; Manufacturer: Yageo America; CompType: Resistor; Value: 67.3; Value_Code: 67R3; Tolerance_%: 0.5; Power_W: 0.1; Value2: 0.1W; VDC_V: 75; TempCo: 50 ppm/C; SizeArea_mm2: 1.28; SizeX_mm: 1.6; SizeY_mm: 0.8; SizeZ_mm: 1; EIA_Code: E192; U/M: EA; AEC Category: Q200
signal-integrity model Resistor
simulation model Resistor
footprint 0603
footprint 0603M
footprint 0603L
footprint 0603_HV
footprint 0603S
pins: 1, 2

## RT0603DRE0768K1L
designator R?  ValueDisplayed: 68.1k  (hidden comment: RT0603DRE0768K1L)
RES, 68.1 k, 0.5%, 0.1 W, 0603; Manufacturer: Yageo America; CompType: Resistor; Value: 68.1k; Res_ohm: 68100; Value_Code: 68k1; Tolerance_%: 0.5; Power_W: 0.1; Value2: 0.1W; VDC_V: 75; TempCo: 50 ppm/C; SizeArea_mm2: 1.28; SizeX_mm: 1.6; SizeY_mm: 0.8; SizeZ_mm: 1; EIA_Code: E192; U/M: EA; AEC Category: Q200
signal-integrity model Resistor
simulation model Resistor
footprint 0603
footprint 0603M
footprint 0603L
footprint 0603_HV
footprint 0603S
pins: 1, 2

## RT0603DRE0768R1L
designator R?  ValueDisplayed: 68.1  (hidden comment: RT0603DRE0768R1L)
RES, 68.1, 0.5%, 0.1 W, 0603; Manufacturer: Yageo America; CompType: Resistor; Value: 68.1; Value_Code: 68R1; Tolerance_%: 0.5; Power_W: 0.1; Value2: 0.1W; VDC_V: 75; TempCo: 50 ppm/C; SizeArea_mm2: 1.28; SizeX_mm: 1.6; SizeY_mm: 0.8; SizeZ_mm: 1; EIA_Code: E192; U/M: EA; AEC Category: Q200
signal-integrity model Resistor
simulation model Resistor
footprint 0603
footprint 0603M
footprint 0603L
footprint 0603_HV
footprint 0603S
pins: 1, 2

## RT0603DRE0769K8L
designator R?  ValueDisplayed: 69.8k  (hidden comment: RT0603DRE0769K8L)
RES, 69.8 k, 0.5%, 0.1 W, 0603; Manufacturer: Yageo America; CompType: Resistor; Value: 69.8k; Res_ohm: 69800; Value_Code: 69k8; Tolerance_%: 0.5; Power_W: 0.1; Value2: 0.1W; VDC_V: 75; TempCo: 50 ppm/C; SizeArea_mm2: 1.28; SizeX_mm: 1.6; SizeY_mm: 0.8; SizeZ_mm: 1; EIA_Code: E192; U/M: EA; AEC Category: Q200
signal-integrity model Resistor
simulation model Resistor
footprint 0603
footprint 0603M
footprint 0603L
footprint 0603_HV
footprint 0603S
pins: 1, 2

## RT0603DRE0769KL
designator R?  ValueDisplayed: 69.0k  (hidden comment: RT0603DRE0769KL)
RES, 69.0 k, 0.5%, 0.1 W, 0603; Manufacturer: Yageo America; CompType: Resistor; Value: 69.0k; Res_ohm: 69000; Value_Code: 69k0; Tolerance_%: 0.5; Power_W: 0.1; Value2: 0.1W; VDC_V: 75; TempCo: 50 ppm/C; SizeArea_mm2: 1.28; SizeX_mm: 1.6; SizeY_mm: 0.8; SizeZ_mm: 1; EIA_Code: E192; U/M: EA; AEC Category: Q200
signal-integrity model Resistor
simulation model Resistor
footprint 0603
footprint 0603M
footprint 0603L
footprint 0603_HV
footprint 0603S
pins: 1, 2

## RT0603DRE0769R8L
designator R?  ValueDisplayed: 69.8  (hidden comment: RT0603DRE0769R8L)
RES, 69.8, 0.5%, 0.1 W, 0603; Manufacturer: Yageo America; CompType: Resistor; Value: 69.8; Value_Code: 69R8; Tolerance_%: 0.5; Power_W: 0.1; Value2: 0.1W; VDC_V: 75; TempCo: 50 ppm/C; SizeArea_mm2: 1.28; SizeX_mm: 1.6; SizeY_mm: 0.8; SizeZ_mm: 1; EIA_Code: E192; U/M: EA; AEC Category: Q200
signal-integrity model Resistor
simulation model Resistor
footprint 0603
footprint 0603M
footprint 0603L
footprint 0603_HV
footprint 0603S
pins: 1, 2

## RT0603DRE0769RL
designator R?  ValueDisplayed: 69.0  (hidden comment: RT0603DRE0769RL)
RES, 69.0, 0.5%, 0.1 W, 0603; Manufacturer: Yageo America; CompType: Resistor; Value: 69.0; Res_ohm: 69; Value_Code: 69R0; Tolerance_%: 0.5; Power_W: 0.1; Value2: 0.1W; VDC_V: 75; TempCo: 50 ppm/C; SizeArea_mm2: 1.28; SizeX_mm: 1.6; SizeY_mm: 0.8; SizeZ_mm: 1; EIA_Code: E192; U/M: EA; AEC Category: Q200
signal-integrity model Resistor
simulation model Resistor
footprint 0603
footprint 0603M
footprint 0603L
footprint 0603_HV
footprint 0603S
pins: 1, 2

## RT0603DRE0770K6L
designator R?  ValueDisplayed: 70.6k  (hidden comment: RT0603DRE0770K6L)
RES, 70.6 k, 0.5%, 0.1 W, 0603; Manufacturer: Yageo America; CompType: Resistor; Value: 70.6k; Res_ohm: 70600; Value_Code: 70k6; Tolerance_%: 0.5; Power_W: 0.1; Value2: 0.1W; VDC_V: 75; TempCo: 50 ppm/C; SizeArea_mm2: 1.28; SizeX_mm: 1.6; SizeY_mm: 0.8; SizeZ_mm: 1; EIA_Code: E192; U/M: EA; AEC Category: Q200
signal-integrity model Resistor
simulation model Resistor
footprint 0603
footprint 0603M
footprint 0603L
footprint 0603_HV
footprint 0603S
pins: 1, 2

## RT0603DRE0770R6L
designator R?  ValueDisplayed: 70.6  (hidden comment: RT0603DRE0770R6L)
RES, 70.6, 0.5%, 0.1 W, 0603; Manufacturer: Yageo America; CompType: Resistor; Value: 70.6; Value_Code: 70R6; Tolerance_%: 0.5; Power_W: 0.1; Value2: 0.1W; VDC_V: 75; TempCo: 50 ppm/C; SizeArea_mm2: 1.28; SizeX_mm: 1.6; SizeY_mm: 0.8; SizeZ_mm: 1; EIA_Code: E192; U/M: EA; AEC Category: Q200
signal-integrity model Resistor
simulation model Resistor
footprint 0603
footprint 0603M
footprint 0603L
footprint 0603_HV
footprint 0603S
pins: 1, 2

## RT0603DRE0771K5L
designator R?  ValueDisplayed: 71.5k  (hidden comment: RT0603DRE0771K5L)
RES, 71.5 k, 0.5%, 0.1 W, 0603; Manufacturer: Yageo America; CompType: Resistor; Value: 71.5k; Res_ohm: 71500; Value_Code: 71k5; Tolerance_%: 0.5; Power_W: 0.1; Value2: 0.1W; VDC_V: 75; TempCo: 50 ppm/C; SizeArea_mm2: 1.28; SizeX_mm: 1.6; SizeY_mm: 0.8; SizeZ_mm: 1; EIA_Code: E192; U/M: EA; AEC Category: Q200
signal-integrity model Resistor
simulation model Resistor
footprint 0603
footprint 0603M
footprint 0603L
footprint 0603_HV
footprint 0603S
pins: 1, 2

## RT0603DRE0771R5L
designator R?  ValueDisplayed: 71.5  (hidden comment: RT0603DRE0771R5L)
RES, 71.5, 0.5%, 0.1 W, 0603; Manufacturer: Yageo America; CompType: Resistor; Value: 71.5; Value_Code: 71R5; Tolerance_%: 0.5; Power_W: 0.1; Value2: 0.1W; VDC_V: 75; TempCo: 50 ppm/C; SizeArea_mm2: 1.28; SizeX_mm: 1.6; SizeY_mm: 0.8; SizeZ_mm: 1; EIA_Code: E192; U/M: EA; AEC Category: Q200
signal-integrity model Resistor
simulation model Resistor
footprint 0603
footprint 0603M
footprint 0603L
footprint 0603_HV
footprint 0603S
pins: 1, 2

## RT0603DRE0772K3L
designator R?  ValueDisplayed: 72.3k  (hidden comment: RT0603DRE0772K3L)
RES, 72.3 k, 0.5%, 0.1 W, 0603; Manufacturer: Yageo America; CompType: Resistor; Value: 72.3k; Res_ohm: 72300; Value_Code: 72k3; Tolerance_%: 0.5; Power_W: 0.1; Value2: 0.1W; VDC_V: 75; TempCo: 50 ppm/C; SizeArea_mm2: 1.28; SizeX_mm: 1.6; SizeY_mm: 0.8; SizeZ_mm: 1; EIA_Code: E192; U/M: EA; AEC Category: Q200
signal-integrity model Resistor
simulation model Resistor
footprint 0603
footprint 0603M
footprint 0603L
footprint 0603_HV
footprint 0603S
pins: 1, 2

## RT0603DRE0772R3L
designator R?  ValueDisplayed: 72.3  (hidden comment: RT0603DRE0772R3L)
RES, 72.3, 0.5%, 0.1 W, 0603; Manufacturer: Yageo America; CompType: Resistor; Value: 72.3; Value_Code: 72R3; Tolerance_%: 0.5; Power_W: 0.1; Value2: 0.1W; VDC_V: 75; TempCo: 50 ppm/C; SizeArea_mm2: 1.28; SizeX_mm: 1.6; SizeY_mm: 0.8; SizeZ_mm: 1; EIA_Code: E192; U/M: EA; AEC Category: Q200
signal-integrity model Resistor
simulation model Resistor
footprint 0603
footprint 0603M
footprint 0603L
footprint 0603_HV
footprint 0603S
pins: 1, 2

## RT0603DRE0773K2L
designator R?  ValueDisplayed: 73.2k  (hidden comment: RT0603DRE0773K2L)
RES, 73.2 k, 0.5%, 0.1 W, 0603; Manufacturer: Yageo America; CompType: Resistor; Value: 73.2k; Res_ohm: 73200; Value_Code: 73k2; Tolerance_%: 0.5; Power_W: 0.1; Value2: 0.1W; VDC_V: 75; TempCo: 50 ppm/C; SizeArea_mm2: 1.28; SizeX_mm: 1.6; SizeY_mm: 0.8; SizeZ_mm: 1; EIA_Code: E192; U/M: EA; AEC Category: Q200
signal-integrity model Resistor
simulation model Resistor
footprint 0603
footprint 0603M
footprint 0603L
footprint 0603_HV
footprint 0603S
pins: 1, 2

## RT0603DRE0773R2L
designator R?  ValueDisplayed: 73.2  (hidden comment: RT0603DRE0773R2L)
RES, 73.2, 0.5%, 0.1 W, 0603; Manufacturer: Yageo America; CompType: Resistor; Value: 73.2; Value_Code: 73R2; Tolerance_%: 0.5; Power_W: 0.1; Value2: 0.1W; VDC_V: 75; TempCo: 50 ppm/C; SizeArea_mm2: 1.28; SizeX_mm: 1.6; SizeY_mm: 0.8; SizeZ_mm: 1; EIA_Code: E192; U/M: EA; AEC Category: Q200
signal-integrity model Resistor
simulation model Resistor
footprint 0603
footprint 0603M
footprint 0603L
footprint 0603_HV
footprint 0603S
pins: 1, 2

## RT0603DRE0774K1L
designator R?  ValueDisplayed: 74.1k  (hidden comment: RT0603DRE0774K1L)
RES, 74.1 k, 0.5%, 0.1 W, 0603; Manufacturer: Yageo America; CompType: Resistor; Value: 74.1k; Res_ohm: 74100; Value_Code: 74k1; Tolerance_%: 0.5; Power_W: 0.1; Value2: 0.1W; VDC_V: 75; TempCo: 50 ppm/C; SizeArea_mm2: 1.28; SizeX_mm: 1.6; SizeY_mm: 0.8; SizeZ_mm: 1; EIA_Code: E192; U/M: EA; AEC Category: Q200
signal-integrity model Resistor
simulation model Resistor
footprint 0603
footprint 0603M
footprint 0603L
footprint 0603_HV
footprint 0603S
pins: 1, 2

## RT0603DRE0774R1L
designator R?  ValueDisplayed: 74.1  (hidden comment: RT0603DRE0774R1L)
RES, 74.1, 0.5%, 0.1 W, 0603; Manufacturer: Yageo America; CompType: Resistor; Value: 74.1; Value_Code: 74R1; Tolerance_%: 0.5; Power_W: 0.1; Value2: 0.1W; VDC_V: 75; TempCo: 50 ppm/C; SizeArea_mm2: 1.28; SizeX_mm: 1.6; SizeY_mm: 0.8; SizeZ_mm: 1; EIA_Code: E192; U/M: EA; AEC Category: Q200
signal-integrity model Resistor
simulation model Resistor
footprint 0603
footprint 0603M
footprint 0603L
footprint 0603_HV
footprint 0603S
pins: 1, 2

## RT0603DRE0775K9L
designator R?  ValueDisplayed: 75.9k  (hidden comment: RT0603DRE0775K9L)
RES, 75.9 k, 0.5%, 0.1 W, 0603; Manufacturer: Yageo America; CompType: Resistor; Value: 75.9k; Res_ohm: 75900; Value_Code: 75k9; Tolerance_%: 0.5; Power_W: 0.1; Value2: 0.1W; VDC_V: 75; TempCo: 50 ppm/C; SizeArea_mm2: 1.28; SizeX_mm: 1.6; SizeY_mm: 0.8; SizeZ_mm: 1; EIA_Code: E192; U/M: EA; AEC Category: Q200
signal-integrity model Resistor
simulation model Resistor
footprint 0603
footprint 0603M
footprint 0603L
footprint 0603_HV
footprint 0603S
pins: 1, 2

## RT0603DRE0775KL
designator R?  ValueDisplayed: 75.0k  (hidden comment: RT0603DRE0775KL)
RES, 75.0 k, 0.5%, 0.1 W, 0603; Manufacturer: Yageo America; CompType: Resistor; Value: 75.0k; Res_ohm: 75000; Value_Code: 75k0; Tolerance_%: 0.5; Power_W: 0.1; Value2: 0.1W; VDC_V: 75; TempCo: 50 ppm/C; SizeArea_mm2: 1.28; SizeX_mm: 1.6; SizeY_mm: 0.8; SizeZ_mm: 1; EIA_Code: E192; U/M: EA; AEC Category: Q200
signal-integrity model Resistor
simulation model Resistor
footprint 0603
footprint 0603M
footprint 0603L
footprint 0603_HV
footprint 0603S
pins: 1, 2

## RT0603DRE0775R9L
designator R?  ValueDisplayed: 75.9  (hidden comment: RT0603DRE0775R9L)
RES, 75.9, 0.5%, 0.1 W, 0603; Manufacturer: Yageo America; CompType: Resistor; Value: 75.9; Value_Code: 75R9; Tolerance_%: 0.5; Power_W: 0.1; Value2: 0.1W; VDC_V: 75; TempCo: 50 ppm/C; SizeArea_mm2: 1.28; SizeX_mm: 1.6; SizeY_mm: 0.8; SizeZ_mm: 1; EIA_Code: E192; U/M: EA; AEC Category: Q200
signal-integrity model Resistor
simulation model Resistor
footprint 0603
footprint 0603M
footprint 0603L
footprint 0603_HV
footprint 0603S
pins: 1, 2

## RT0603DRE0775RL
designator R?  ValueDisplayed: 75.0  (hidden comment: RT0603DRE0775RL)
RES, 75.0, 0.5%, 0.1 W, 0603; Manufacturer: Yageo America; CompType: Resistor; Value: 75.0; Res_ohm: 75; Value_Code: 75R0; Tolerance_%: 0.5; Power_W: 0.1; Value2: 0.1W; TempCo: 50 ppm/C; SizeArea_mm2: 1.28; SizeX_mm: 1.6; SizeY_mm: 0.8; SizeZ_mm: 1; EIA_Code: E192; U/M: EA; AEC Category: Q200
signal-integrity model Resistor
simulation model Resistor
footprint 0603
footprint 0603M
footprint 0603L
footprint 0603_HV
footprint 0603S
pins: 1, 2

## RT0603DRE0776K8L
designator R?  ValueDisplayed: 76.8k  (hidden comment: RT0603DRE0776K8L)
RES, 76.8 k, 0.5%, 0.1 W, 0603; Manufacturer: Yageo America; CompType: Resistor; Value: 76.8k; Res_ohm: 76800; Value_Code: 76k8; Tolerance_%: 0.5; Power_W: 0.1; Value2: 0.1W; VDC_V: 75; TempCo: 50 ppm/C; SizeArea_mm2: 1.28; SizeX_mm: 1.6; SizeY_mm: 0.8; SizeZ_mm: 1; EIA_Code: E192; U/M: EA; AEC Category: Q200
signal-integrity model Resistor
simulation model Resistor
footprint 0603
footprint 0603M
footprint 0603L
footprint 0603_HV
footprint 0603S
pins: 1, 2

## RT0603DRE0776R8L
designator R?  ValueDisplayed: 76.8  (hidden comment: RT0603DRE0776R8L)
RES, 76.8, 0.5%, 0.1 W, 0603; Manufacturer: Yageo America; CompType: Resistor; Value: 76.8; Value_Code: 76R8; Tolerance_%: 0.5; Power_W: 0.1; Value2: 0.1W; VDC_V: 75; TempCo: 50 ppm/C; SizeArea_mm2: 1.28; SizeX_mm: 1.6; SizeY_mm: 0.8; SizeZ_mm: 1; EIA_Code: E192; U/M: EA; AEC Category: Q200
signal-integrity model Resistor
simulation model Resistor
footprint 0603
footprint 0603M
footprint 0603L
footprint 0603_HV
footprint 0603S
pins: 1, 2

## RT0603DRE0777K7L
designator R?  ValueDisplayed: 77.7k  (hidden comment: RT0603DRE0777K7L)
RES, 77.7 k, 0.5%, 0.1 W, 0603; Manufacturer: Yageo America; CompType: Resistor; Value: 77.7k; Res_ohm: 77700; Value_Code: 77k7; Tolerance_%: 0.5; Power_W: 0.1; Value2: 0.1W; VDC_V: 75; TempCo: 50 ppm/C; SizeArea_mm2: 1.28; SizeX_mm: 1.6; SizeY_mm: 0.8; SizeZ_mm: 1; EIA_Code: E192; U/M: EA; AEC Category: Q200
signal-integrity model Resistor
simulation model Resistor
footprint 0603
footprint 0603M
footprint 0603L
footprint 0603_HV
footprint 0603S
pins: 1, 2

## RT0603DRE0777R7L
designator R?  ValueDisplayed: 77.7  (hidden comment: RT0603DRE0777R7L)
RES, 77.7, 0.5%, 0.1 W, 0603; Manufacturer: Yageo America; CompType: Resistor; Value: 77.7; Value_Code: 77R7; Tolerance_%: 0.5; Power_W: 0.1; Value2: 0.1W; VDC_V: 75; TempCo: 50 ppm/C; SizeArea_mm2: 1.28; SizeX_mm: 1.6; SizeY_mm: 0.8; SizeZ_mm: 1; EIA_Code: E192; U/M: EA; AEC Category: Q200
signal-integrity model Resistor
simulation model Resistor
footprint 0603
footprint 0603M
footprint 0603L
footprint 0603_HV
footprint 0603S
pins: 1, 2

## RT0603DRE0778K7L
designator R?  ValueDisplayed: 78.7k  (hidden comment: RT0603DRE0778K7L)
RES, 78.7 k, 0.5%, 0.1 W, 0603; Manufacturer: Yageo America; CompType: Resistor; Value: 78.7k; Res_ohm: 78700; Value_Code: 78k7; Tolerance_%: 0.5; Power_W: 0.1; Value2: 0.1W; VDC_V: 75; TempCo: 50 ppm/C; SizeArea_mm2: 1.28; SizeX_mm: 1.6; SizeY_mm: 0.8; SizeZ_mm: 1; EIA_Code: E192; U/M: EA; AEC Category: Q200
signal-integrity model Resistor
simulation model Resistor
footprint 0603
footprint 0603M
footprint 0603L
footprint 0603_HV
footprint 0603S
pins: 1, 2

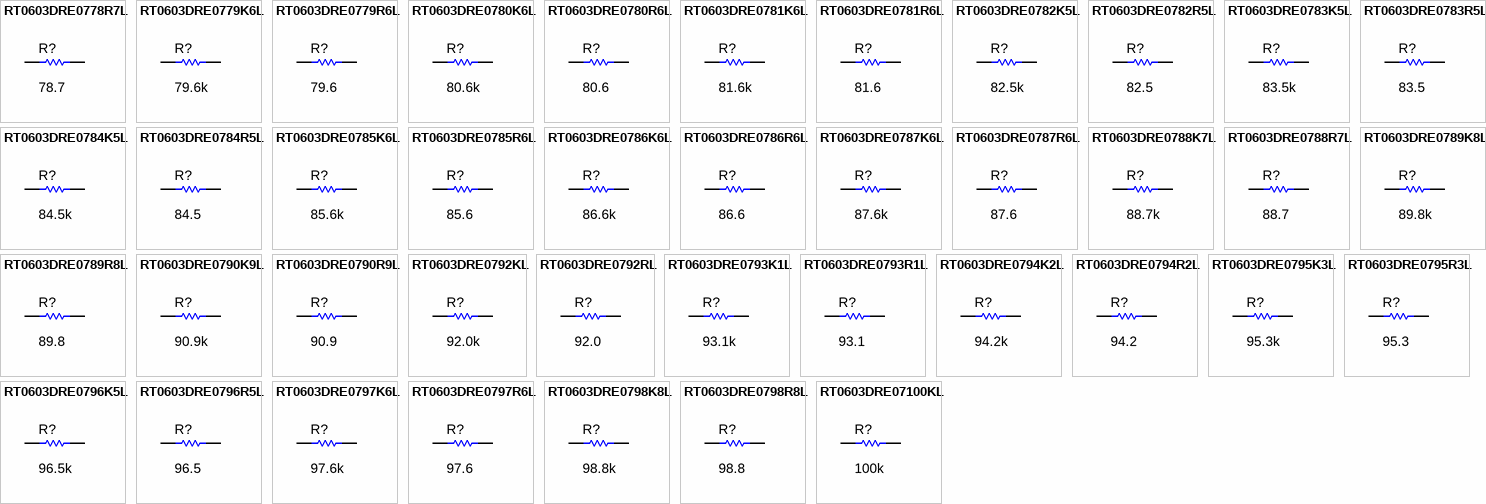
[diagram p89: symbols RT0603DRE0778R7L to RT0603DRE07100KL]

## RT0603DRE0778R7L
designator R?  ValueDisplayed: 78.7  (hidden comment: RT0603DRE0778R7L)
RES, 78.7, 0.5%, 0.1 W, 0603; Manufacturer: Yageo America; CompType: Resistor; Value: 78.7; Value_Code: 78R7; Tolerance_%: 0.5; Power_W: 0.1; Value2: 0.1W; VDC_V: 75; TempCo: 50 ppm/C; SizeArea_mm2: 1.28; SizeX_mm: 1.6; SizeY_mm: 0.8; SizeZ_mm: 1; EIA_Code: E192; U/M: EA; AEC Category: Q200
signal-integrity model Resistor
simulation model Resistor
footprint 0603
footprint 0603M
footprint 0603L
footprint 0603_HV
footprint 0603S
pins: 1, 2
